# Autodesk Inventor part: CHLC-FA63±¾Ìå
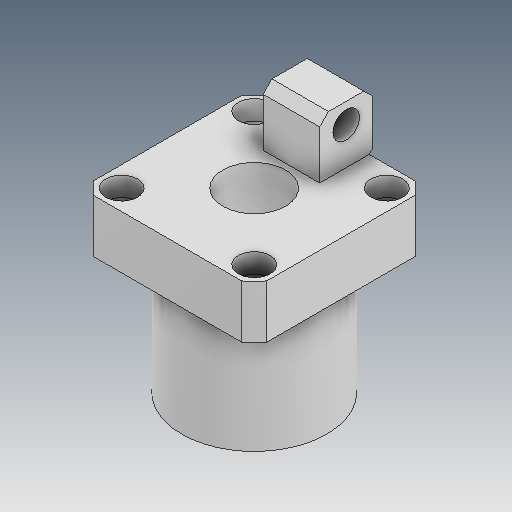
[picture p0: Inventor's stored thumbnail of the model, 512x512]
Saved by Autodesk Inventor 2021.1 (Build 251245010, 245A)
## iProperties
Created: 2021-05
Part Number: CHLC-FA63±¾Ìå
Material: Ogólny
Document SubType Name: Modeling
Designer: user
Density: 1 g/cm^3
Appearance: Domyślna
Author: user
Revision Number: ÈÎºÎ
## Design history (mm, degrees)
feature "ÊäÈë1"
node "Bryła1"
